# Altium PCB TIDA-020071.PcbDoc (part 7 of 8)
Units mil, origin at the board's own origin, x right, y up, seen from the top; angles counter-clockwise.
Board outline 5750 x 4050 mil, 6 copper layers (Top Layer, GND PLANE-1, SIGNAL LAYER, SIGNAL/POWER LAYER, GND PLANE-2, Bottom Layer), stack 59.616 mil thick; 776 components, 498 nets, 2205 pads, 871 vias.
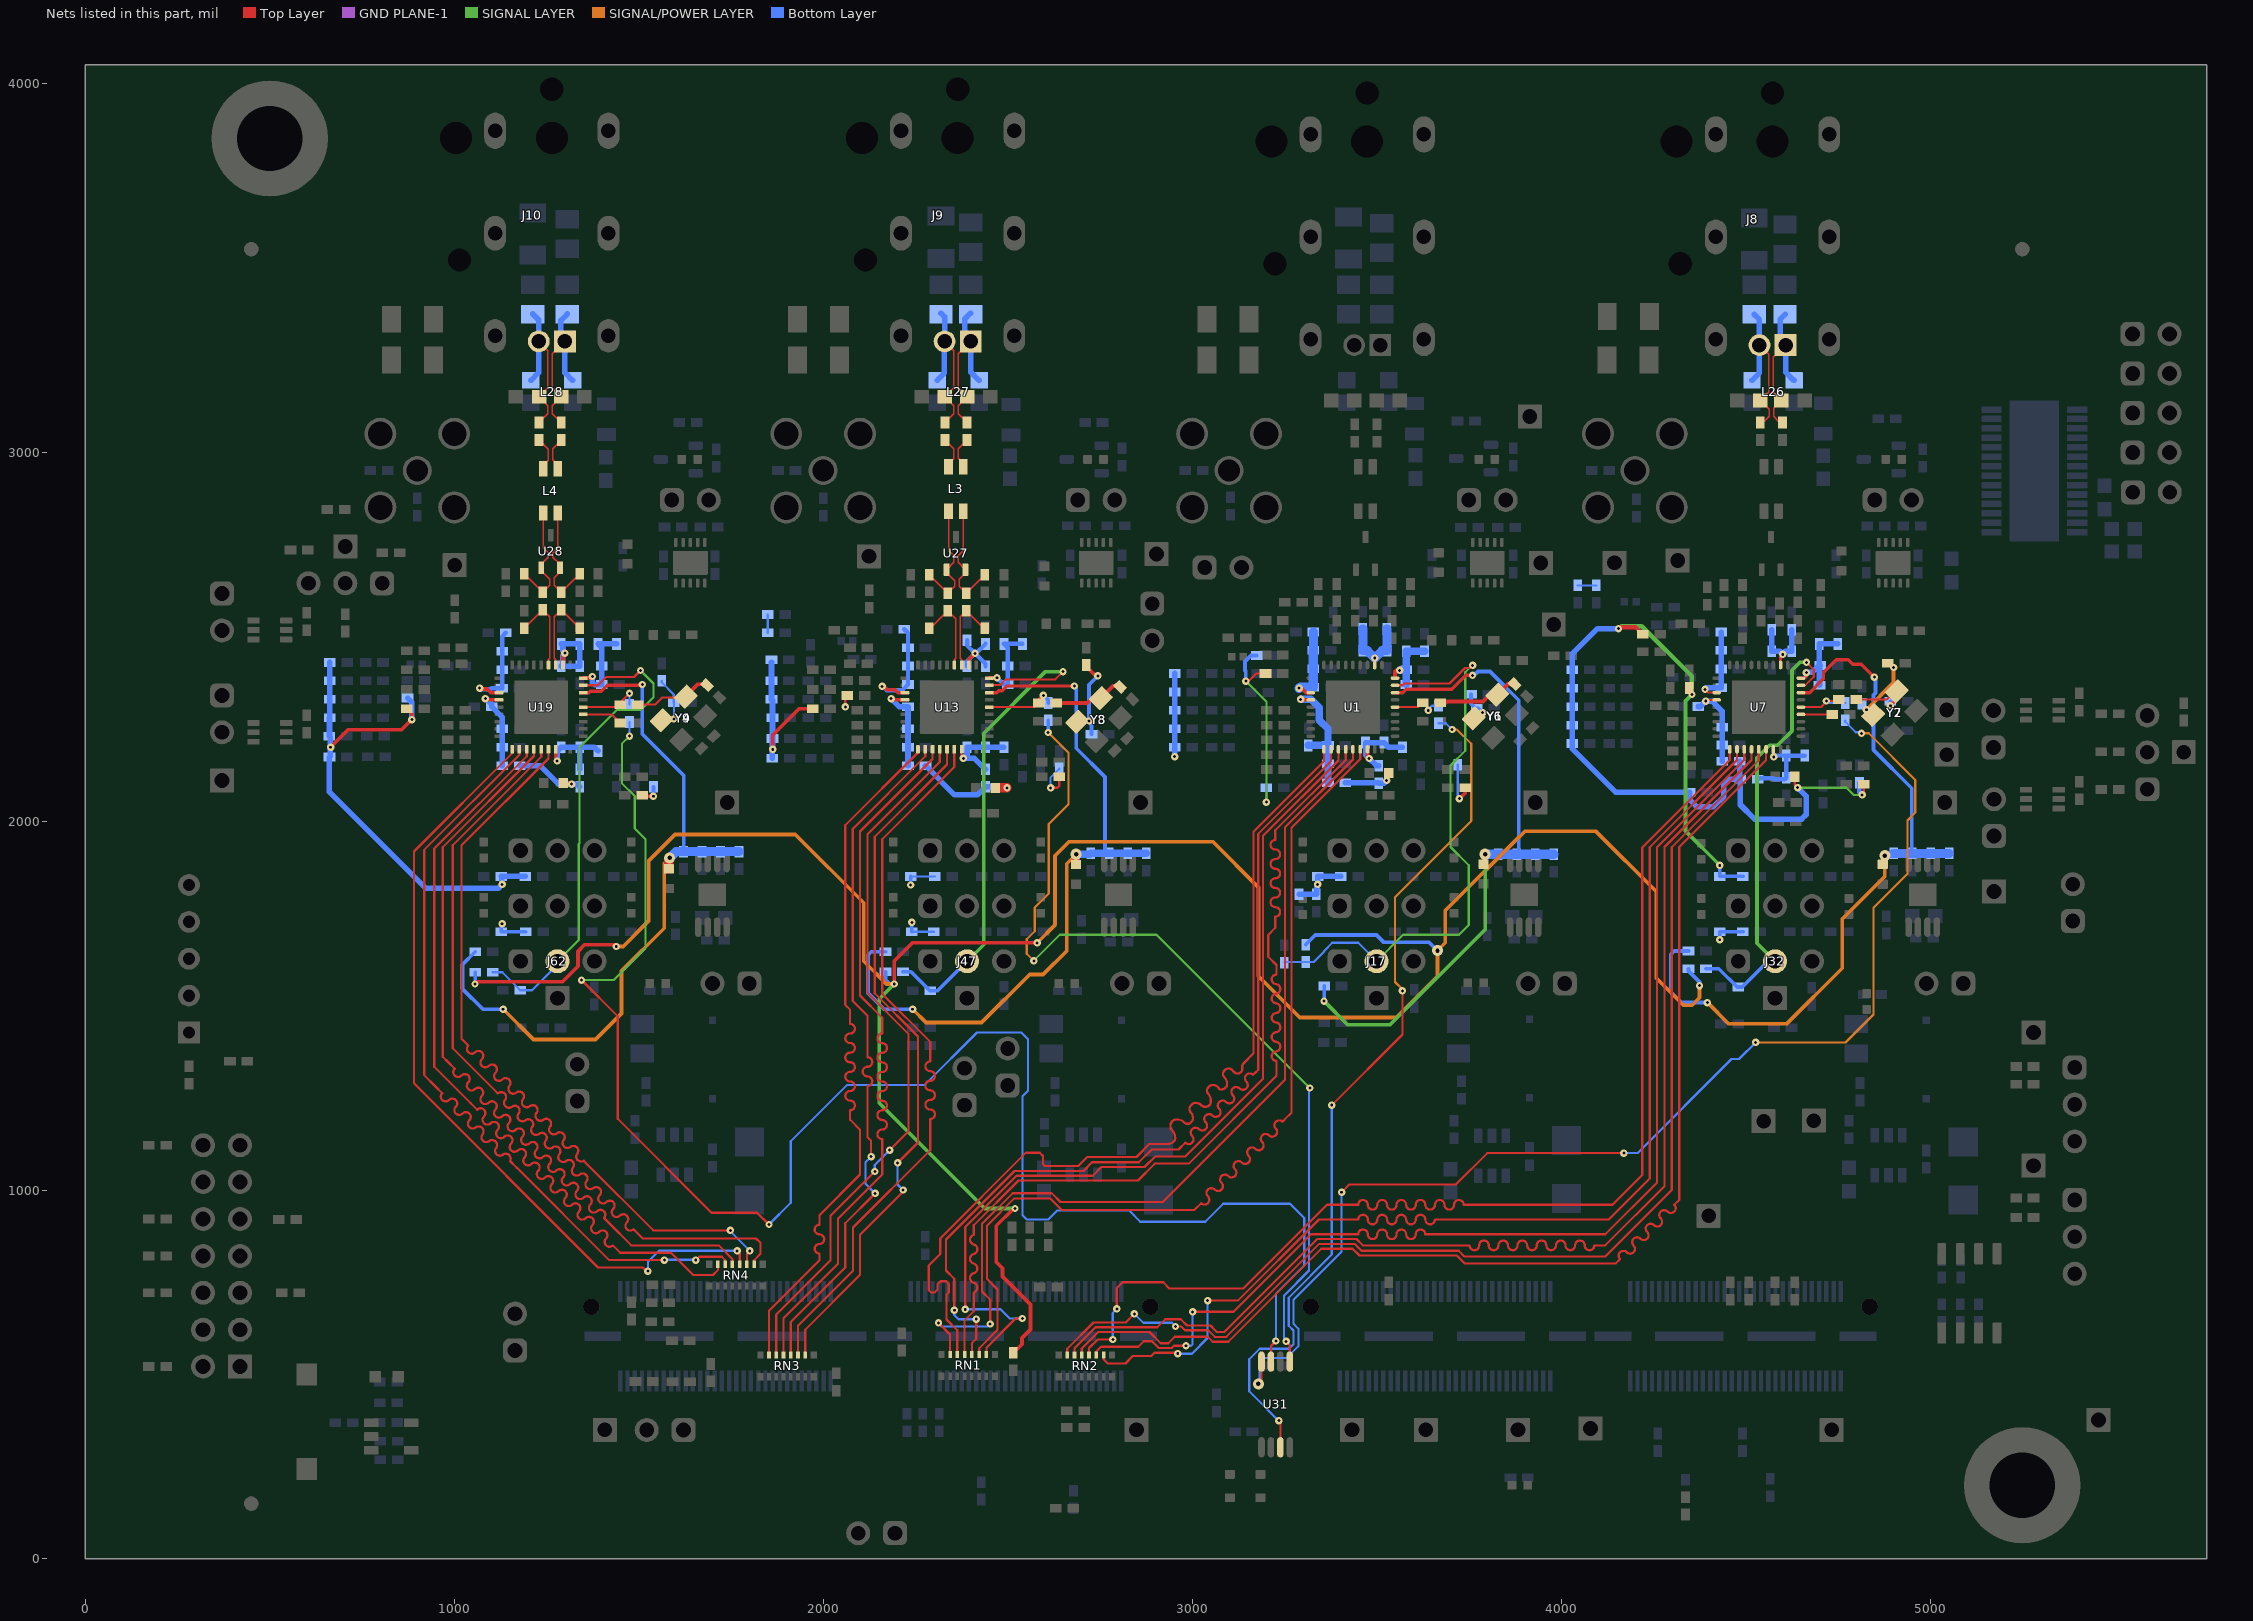
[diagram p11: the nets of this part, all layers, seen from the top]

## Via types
v1: diameter 20, hole 8, Top Layer to Bottom Layer, tented both sides, 637 vias
v2: diameter 30, hole 12, Top Layer to Bottom Layer, tented both sides, 105 vias
v3: diameter 19.68, hole 7.87, Top Layer to Bottom Layer, tented bottom, 68 vias
v4: diameter 19.68, hole 7.87, Top Layer to Bottom Layer, 25 vias
v5: diameter 24, hole 8, Top Layer to Bottom Layer, tented both sides, 24 vias
v6: diameter 19.68, hole 7.87, Top Layer to Bottom Layer, tented both sides, 12 vias

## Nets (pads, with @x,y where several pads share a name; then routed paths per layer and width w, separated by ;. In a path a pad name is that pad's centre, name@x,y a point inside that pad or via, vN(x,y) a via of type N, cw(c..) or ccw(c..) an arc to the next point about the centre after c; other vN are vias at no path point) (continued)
TRD2C_N: C152.1 D35.1 J8.2 L26.4 R237.2 | length 446.9
  Top Layer w4: J8.2@4537.64,3290 4562.5,3265.13 4562.5,3162.5 D35.1@4540,3140 4564,3116 4564,3096.56 4549.44,3082 4542,3082 C152.1@4540,3080
  Bottom Layer w15: L26.4@4517.42,3194.51 4537.32,3214.41 4537.32,3289.68 J8.2@4537.64,3290 4537.64,3359.16 R237.2@4523.48,3373.31
TRD2C_P: C153.1 D36.2 J8.1 L26.1 R236.2 | length 456.7
  Top Layer w4: C153.1@4600,3080 4598,3082 4590.56,3082 4576,3096.56 4576,3118.99 D36.2@4597.01,3140 4574.5,3162.5 4574.5,3256.5 4608,3290 J8.1@4608.5,3290
  Bottom Layer w15: R236.2@4607.16,3373.22 4594.29,3360.34 4594.29,3304.22 J8.1@4608.5,3290 4608.5,3216.63 4630.63,3194.51 L26.1@4631.59,3194.51
TRD3_N: C159.2 R243.2 U13.13 | length 227.3
  Top Layer w4: C159.2@2287.64,2522.76 2289.64,2524.76 2292.39,2524.76 R243.2@2337.64,2570 2339.64,2568 2359.35,2548.3 2359.35,2440.57 2355.51,2436.72 U13.13@2355.51,2422.91
TRD3_P: C160.1 R244.2 U13.12 | length 225
  Top Layer w4: U13.12@2375.2,2422.91 2375.2,2436.72 2371.35,2440.57 2371.35,2553.72 R244.2@2387.64,2570 2432.88,2524.76 2435.64,2524.76 C160.1@2437.64,2522.76
TRD3A_N: L3.4 R243.1 R245.1 U27.1 | length 324.4
  Top Layer w4: R245.1@2287.64,2667.24 R243.1@2337.64,2617.24 2356.64,2636.24 2356.64,2650.86 2334.41,2673.09 U27.1@2334.41,2681.42 2354,2701.01 2354,2719.2 2352.2,2721 2352.13,2721 2340,2733.13 L3.4@2340,2839.92
TRD3A_P: L3.1 R244.1 R246.2 U27.2 | length 322
  Top Layer w4: L3.1@2379.37,2839.92 2379.37,2732.5 2367.87,2721 2367.8,2721 2366,2719.2 2366,2701.01 U27.2@2385.59,2681.42 2385.59,2672.09 2368.64,2655.14 2368.64,2636.24 R244.1@2387.64,2617.24 R246.2@2437.64,2667.24
TRD3B_N: C163.2 L3.3 | length 88.2
  Top Layer w4: C163.2@2330,3032.76 2353.68,3009.07 2353.68,2982.18 2340,2968.5 L3.3@2340,2960
TRD3B_P: C164.2 L3.2 | length 88.5
  Top Layer w4: L3.2@2379.37,2960 2379.37,2969.63 2365.68,2983.31 2365.68,3008.44 C164.2@2390,3032.76
TRD3C_N: C163.1 D37.1 J9.2 L27.4 R248.2 | length 454.7
  Top Layer w4: J9.2@2329.13,3300 2354,3275.13 2354,3174 D37.1@2330,3150 2354,3126 2354,3104 C163.1@2330,3080
  Bottom Layer w15: L27.4@2308.91,3194.51 2328.82,3214.41 2328.82,3299.68 J9.2@2329.13,3300 2329.13,3366.55 R248.2@2319.11,3376.57
TRD3C_P: C164.1 D38.2 J9.1 L27.1 R247.2 | length 470.2
  Top Layer w4: C164.1@2390,3080 2366,3104 2366,3126 D38.2@2390,3150 2366,3174 2366,3266.5 2399.5,3300 J9.1@2400,3300
  Bottom Layer w15: R247.2@2399.79,3376.57 2383.22,3360 2383.22,3316.78 J9.1@2400,3300 2400,3216.63 2422.12,3194.51 L27.1@2423.09,3194.51
TRD4_N: C167.2 R251.2 U19.13 | length 230.2
  Top Layer w4: C167.2@1190,2522.76 R251.2@1240,2572.76 1259.35,2553.4 1259.35,2440.57 1255.51,2436.72 U19.13@1255.51,2422.91
TRD4_P: C168.2 R252.2 U19.12 | length 229.9
  Top Layer w4: U19.12@1275.2,2422.91 1275.2,2436.72 1271.35,2440.57 1271.35,2554.11 R252.2@1290,2572.76 C168.2@1340,2522.76
TRD4A_N: L4.4 R251.1 R253.1 U28.1 | length 317.2
  Top Layer w4: R253.1@1190,2670 R251.1@1240,2620 1259,2639 1259,2655.1 1235.92,2678.18 U28.1@1235.92,2686.42 1235.92,2695.5 1255.51,2715.09 1255.51,2726.94 1241.14,2741.32 L4.4@1241.14,2835.04
TRD4A_P: L4.1 R252.1 R254.1 U28.2 | length 313.8
  Top Layer w4: L4.1@1280.51,2835.04 1280.51,2755.69 1280.51,2739.94 1280.51,2739.11 1267.51,2726.11 1267.51,2715.49 1287.1,2695.9 U28.2@1287.1,2686.42 1287.1,2675.3 1271,2659.2 1271,2639 R252.1@1290,2620 R254.1@1340,2670
TRD4B_N: C171.2 L4.3 | length 93.6
  Top Layer w4: C171.2@1230,3032.76 1254.83,3007.93 1254.83,2977.83 1241.14,2964.14 L4.3@1241.14,2955.12
TRD4B_P: C172.2 L4.2 | length 92.9
  Top Layer w4: L4.2@1280.51,2955.12 1280.51,2965.39 1266.83,2979.07 1266.83,3009.58 C172.2@1290,3032.76
TRD4C_N: C171.1 D39.1 J10.2 L28.4 R256.2 | length 456.1
  Top Layer w4: J10.2@1229.13,3300 1254,3275.13 1254,3174 D39.1@1230,3150 1254,3126 1254,3104 C171.1@1230,3080
  Bottom Layer w15: L28.4@1207.48,3194.51 1208.44,3194.51 1229.08,3215.15 1229.08,3216.11 1229.13,3216.16 J10.2@1229.13,3300 1229.13,3358.13 R256.2@1212.98,3374.28
TRD4C_P: C172.1 D40.2 J10.1 L28.1 R255.2 | length 465.2
  Top Layer w4: C172.1@1290,3080 1266,3104 1266,3126 D40.2@1290,3150 1266,3174 1266,3266.7 1299.3,3300 J10.1@1300,3300
  Bottom Layer w15: R255.2@1306.77,3374.28 1289.41,3356.92 1289.41,3310.59 J10.1@1300,3300 1300,3215.2 1320.69,3194.51 L28.1@1321.65,3194.51
TX_CLK-1: RN1.14 U1.28 | length 2626.2
  Top Layer w6: RN1.14@2363.73,554.39 2363.73,620 2334.41,649.32 2334.41,716.51 2340.6,722.7 2340.6,745.47 2333.57,752.5 2318,752.5 2309.9,744.4 2309.9,729.8 2302.7,722.6 2292.02,722.6 2286,728.62 2286,795.5 2317.1,826.6 2317.1,868.46 2549.44,1100.8 2587,1100.8 2595.6,1092.2 2595.6,1070 2600.6,1065 2691.4,1065 2716.1,1089.7 2849.14,1089.7 2884.54,1125.1 2934.93,1125.1 ccw(c2934.93,1146.27) 2949.9,1131.3 ccw(c2939.28,1141.92) 2954.3,1141.92 ccw(c2928.11,1141.92) 2950.91,1154.81 ccw(c2928.11,1141.92) 2946.63,1160.44 cw(c2958.99,1172.81) 2941.51,1172.81 2941.51,1174.7 cw(c2958.21,1174.7) 2946.4,1186.51 cw(c2958.2,1174.72) 2958.2,1191.4 cw(c2958.2,1162.18) 2978.86,1182.84 ccw(c2987.65,1191.63) 2978.9,1182.8 ccw(c2987.65,1191.63) 2987.65,1179.2 ccw(c2987.65,1191.88) 2996.61,1182.91 2998.64,1184.93 ccw(c2990.27,1193.3) 3002.1,1193.3 3002.1,1196.4 ccw(c2982.3,1196.4) 3000.44,1204.34 ccw(c2982.3,1196.4) 2996.3,1210.4 cw(c3004.75,1218.85) 2992.8,1218.85 cw(c3007.89,1218.85) 2997.22,1229.52 3000.17,1232.47 cw(c3009.5,1223.15) 3009.5,1236.34 cw(c3009.5,1215.18) 3024.46,1230.14 ccw(c3036.15,1241.83) 3025.38,1229.28 ccw(c3036.15,1241.83) 3036.15,1225.3 ccw(c3036.15,1239.43) 3046.14,1229.44 ccw(c3035.61,1239.97) 3050.5,1239.97 3050.5,1243.78 ccw(c3025.58,1243.78) 3048.83,1252.73 ccw(c3025.58,1243.78) 3043.2,1261.4 cw(c3049.96,1268.16) 3040.4,1268.16 cw(c3057.4,1268.16) 3045.38,1280.18 cw(c3056.78,1268.78) 3056.78,1284.9 cw(c3056.78,1269.15) 3067.91,1280.29 3074.34,1273.86 ccw(c3078.1,1277.61) 3078.1,1272.3 ccw(c3078.1,1288.72) 3089.71,1277.11 3092.85,1280.25 ccw(c3087.9,1285.2) 3094.9,1285.2 3094.9,1287.42 ccw(c3070.32,1287.42) 3093,1296.9 ccw(c3070.32,1287.42) 3087.7,1304.8 cw(c3097.84,1314.94) 3083.5,1314.94 cw(c3096.2,1314.94) 3087.21,1323.91 3088.17,1324.87 cw(c3099.1,1313.95) 3099.1,1329.4 cw(c3099.1,1316.6) 3108.15,1325.65 3113.77,1320.03 ccw(c3123.5,1329.76) 3115.02,1318.92 ccw(c3123.5,1329.76) 3123.5,1316 ccw(c3123.5,1329.04) 3132.72,1319.82 ccw(c3125.28,1327.26) 3135.8,1327.26 3135.8,1335.17 cw(c3146.73,1335.17) 3139,1342.9 3166,1369.9 3166,1970.44 3357.09,2161.53 U1.28@3357.09,2194.57
TX_CLK-2: RN2.12 U7.28 | length 3216.6
  Top Layer w6: RN2.12@2720.67,553.15 2720.67,571.58 2744.09,595 v1(2785,595) ; v1(2796,678) 2796,734.7 2811.1,749.8 2921.56,749.8 2938.29,733.06 3138.36,733.06 3365.29,960 3450,960 cw(c3463,960) 3476,960 ccw(c3489,960) 3502,960 cw(c3515,960) 3528,960 ccw(c3541,960) 3554,960 cw(c3567,960) 3580,960 ccw(c3593,960) 3606,960 cw(c3619,960) 3632,960 ccw(c3645,960) 3658,960 cw(c3671,960) 3684,960 ccw(c3697,960) 3710,960 cw(c3723,960) 3736,960 3740,960 4139.2,960 4220,1040.8 4220,1928.42 4457.09,2165.5 U7.28@4457.09,2194.57
  Bottom Layer w6: v1(2785,595) 2785,667 v1(2796,678)
TX_CLK-3: RN3.15 U13.28 | length 2020
  Top Layer w6: RN3.15@1853.13,553.15 1853.13,673.13 1990,810 1990,827.79 cw(c1990,840.79) 1990,853.79 ccw(c1990,866.79) 1990,879.79 cw(c1990,892.79) 1990,905.79 1990,931.79 2100,1041.79 2100,1163.37 2073.09,1190.28 2073.09,1216.28 ccw(c2073.09,1229.28) 2073.09,1242.28 cw(c2073.09,1255.28) 2073.09,1268.28 ccw(c2073.09,1281.28) 2073.09,1294.28 cw(c2073.09,1307.28) 2073.09,1320.28 ccw(c2073.09,1333.28) 2073.09,1346.28 cw(c2073.09,1359.28) 2073.09,1372.28 ccw(c2073.09,1385.28) 2073.09,1398.28 cw(c2073.09,1411.28) 2073.09,1424.28 ccw(c2073.09,1437.28) 2073.09,1450.28 2073.09,1472.77 2073.09,1488.37 2060,1501.46 2060,1988.82 2257.09,2185.9 U13.28@2257.09,2194.57
TX_CLK-4: RN4.4 U19.28 | length 2179
  Top Layer w6: U19.28@1157.09,2194.57 1157.09,2183.82 891,1917.73 891,1289 1389.79,790.21 1511.27,790.21 1521.48,780 v1(1525,780) ; v1(1766.95,835.17) 1773.7,828.42 RN4.4@1773.7,799.05
  Bottom Layer w6: v1(1525,780) 1525,805 1555.17,835.17 v1(1766.95,835.17)
TX_CTRL-1: RN1.12 U1.29 | length 2514.3
  Top Layer w6: v1(2355.51,674.14) 2355.51,759.29 2332.9,781.9 2332.9,865.87 2518.87,1051.84 2705.54,1051.84 2728.9,1075.2 2855.51,1075.2 2890.26,1109.94 2963.14,1109.94 2981.53,1128.33 ccw(c2990.72,1137.52) 2999.91,1146.71 cw(c3009.1,1155.9) 3018.3,1165.1 ccw(c3027.49,1174.29) 3036.68,1183.48 cw(c3045.87,1192.67) 3055.07,1201.87 ccw(c3064.26,1211.06) 3073.45,1220.25 cw(c3082.64,1229.44) 3091.84,1238.64 ccw(c3101.03,1247.83) 3110.22,1257.02 cw(c3119.41,1266.21) 3128.61,1275.41 ccw(c3137.8,1284.6) 3146.99,1293.79 cw(c3156.18,1302.98) 3165.38,1312.17 3171.5,1318.3 3179.2,1326 3179.2,1965.26 3376.77,2162.83 U1.29@3376.77,2194.57 ; RN1.12@2403.1,554.39 2403.1,584.87 2415,596.76 v1(2415,650)
  Bottom Layer w6: v1(2355.51,674.14) 2355.51,661.47 2366.98,650 v1(2415,650)
TX_CTRL-2: RN2.10 U7.29 | length 3146
  Top Layer w6: RN2.10@2760.04,553.15 2760.04,540.98 2771.08,529.94 2819.33,529.94 2839.38,550 2889.14,550 2898.14,559 2958.5,559 v1(2961,556.5) ; v1(3041.9,700.2) 3123.88,700.2 3343.68,920 3450,920 cw(c3463,920) 3476,920 ccw(c3489,920) 3502,920 cw(c3515,920) 3528,920 ccw(c3541,920) 3554,920 cw(c3567,920) 3580,920 ccw(c3593,920) 3606,920 cw(c3619,920) 3632,920 ccw(c3645,920) 3658,920 3660,920 4128.9,920 4240,1031.1 4240,1928.79 4476.77,2165.57 U7.29@4476.77,2194.57
  Bottom Layer w6: v1(2961,556.5) 2999.5,556.5 3041.9,598.9 v1(3041.9,700.2)
TX_CTRL-3: RN3.12 U13.29 | length 1900.1
  Top Layer w6: RN3.12@1912.18,553.15 1912.18,642.18 2060,790 2060,910.07 v1(2140.73,990.8) ; v1(2130,1090.5) 2130,1132.83 2120,1142.83 2120,1270 2120,1282 ccw(c2120,1295) 2120,1308 cw(c2120,1321) 2120,1334 ccw(c2120,1347) 2120,1360 2120,1472.19 2080,1512.19 2080,1978.71 2276.77,2175.48 U13.29@2276.77,2194.57
  Bottom Layer w6: v1(2130,1090.5) 2114.57,1075.07 2114.57,1016.96 v1(2140.73,990.8)
TX_CTRL-4: RN4.6 U19.29 | length 2163.2
  Top Layer w6: U19.29@1176.77,2194.57 1176.77,2180 918.62,1921.85 918.62,1311.38 949.19,1280.81 967.58,1262.42 ccw(c976.77,1253.23) 985.96,1244.04 cw(c995.15,1234.85) 1004.35,1225.65 ccw(c1013.54,1216.46) 1022.73,1207.27 cw(c1031.92,1198.08) 1041.12,1188.88 ccw(c1050.31,1179.69) 1059.5,1170.5 cw(c1066.15,1158.76) 1077.89,1152.11 ccw(c1087.08,1142.92) 1096.27,1133.73 cw(c1102.76,1121.83) 1114.66,1115.34 ccw(c1123.85,1106.15) 1133.04,1096.96 cw(c1139.53,1085.06) 1151.42,1078.57 1169.81,1060.19 1170,1060 1420,810 v1(1569.86,810) ; v1(1654.71,810) 1655.1,810 1664,818.9 1725.14,818.9 1734.33,809.71 RN4.6@1734.33,799.05
  Bottom Layer w6: v1(1569.86,810) 1571.04,811.18 1653.52,811.18 v1(1654.71,810)
TX_D0-1: RN1.11 U1.33 | length 2600.3
  Top Layer w6: RN1.11@2422.79,554.39 2422.79,571.53 2472.76,621.5 2472.76,730.24 2443.8,759.2 2443.8,903.24 2517.96,977.4 2614.9,977.4 2646.3,946 3006,946 3024.38,964.38 ccw(c3033.58,973.58) 3042.77,982.77 cw(c3051.96,991.96) 3061.15,1001.15 ccw(c3070.35,1010.35) 3079.54,1019.54 cw(c3088.73,1028.73) 3097.92,1037.92 ccw(c3107.12,1047.12) 3116.31,1056.31 cw(c3125.5,1065.5) 3134.69,1074.69 ccw(c3143.89,1083.89) 3153.08,1093.08 cw(c3162.27,1102.27) 3171.46,1111.46 ccw(c3180.66,1120.65) 3189.85,1129.85 cw(c3199.04,1139.04) 3208.23,1148.23 ccw(c3217.42,1157.42) 3226.62,1166.62 cw(c3235.81,1175.81) 3245,1185 3250,1190 3250,1190.25 3269.1,1209.35 3269.1,1981.62 3455.51,2168.03 U1.33@3455.51,2194.57
TX_D0-2: RN2.13 U7.33 | length 3309.7
  Top Layer w6: RN2.13@2700.99,553.15 2700.99,570.28 2745.71,615 2884.64,615 2914.64,585 2935.36,585 2952.86,602.5 3042.45,602.5 3055.95,589 3098,589 3350,841 3434.91,841 3453.53,822.38 3575.24,822.38 3575.3,822.44 3598.49,822.44 3598.55,822.38 3717.08,822.38 3738.27,801.19 4147.96,801.19 4156.77,810 4159.69,812.92 cw(c4168.89,822.11) 4178.08,831.31 ccw(c4187.27,840.5) 4196.46,849.69 cw(c4205.66,858.88) 4214.85,868.08 ccw(c4224.04,877.27) 4233.23,886.46 cw(c4242.43,895.65) 4251.62,904.85 ccw(c4260.81,914.04) 4270,923.23 cw(c4279.19,932.42) 4288.39,941.61 ccw(c4297.58,950.81) 4306.77,960 4320,973.23 4320,1929.5 4555.51,2165.01 U7.33@4555.51,2194.57
TX_D0-3: RN3.11 U13.33 | length 2013.6
  Top Layer w6: RN3.11@1931.87,553.15 1931.87,631.87 2081.12,781.12 2081.12,898.61 2290,1107.5 2290,1166.23 2290,1192.23 ccw(c2290,1205.23) 2290,1218.23 cw(c2290,1231.23) 2290,1244.23 ccw(c2290,1257.23) 2290,1270.23 cw(c2290,1283.23) 2290,1296.23 ccw(c2290,1309.23) 2290,1322.23 cw(c2290,1335.23) 2290,1348.23 2290,1370 2290,1401.52 2160,1531.52 2160,1951.01 2355.51,2146.52 U13.33@2355.51,2194.57
TX_D0-4: RN4.3 U19.33 | length 2161.7
  Top Layer w6: U19.33@1255.51,2194.57 1255.51,2169.76 1020,1934.25 1020,1410 1038.38,1391.61 ccw(c1047.58,1382.42) 1056.77,1373.23 cw(c1065.96,1364.04) 1075.15,1354.85 ccw(c1084.35,1345.65) 1093.54,1336.46 cw(c1102.73,1327.27) 1111.92,1318.08 ccw(c1121.12,1308.88) 1130.31,1299.69 cw(c1139.5,1290.5) 1148.69,1281.31 ccw(c1160.27,1274.5) 1167.08,1262.92 cw(c1176.27,1253.73) 1185.46,1244.54 ccw(c1197.04,1237.73) 1203.85,1226.15 cw(c1213.04,1216.96) 1222.23,1207.77 ccw(c1233.81,1200.96) 1240.62,1189.38 cw(c1249.81,1180.19) 1259,1171 ccw(c1270.58,1164.19) 1277.39,1152.61 cw(c1286.58,1143.42) 1295.77,1134.23 ccw(c1307.35,1127.42) 1314.16,1115.84 cw(c1323.35,1106.65) 1332.54,1097.46 ccw(c1344.12,1090.65) 1350.93,1079.07 1360,1070 1539.39,890.61 v1(1748.35,890.61) ; RN4.3@1793.38,799.05 1793.38,827.43 v1(1801.12,835.17)
  Bottom Layer w6: v1(1748.35,890.61) 1748.35,887.93 v1(1801.12,835.17)
TX_D1-1: RN1.15 U1.32 | length 2501.7
  Top Layer w6: v1(2312.55,639.79) 2312.76,640 2344.05,608.71 RN1.15@2344.05,554.39 ; v1(2452.76,636.83) 2452.76,702.74 2430.8,724.7 2430.8,908.62 2513.68,991.5 2619.19,991.5 2643.32,967.37 2920.77,967.37 3252,1298.6 3252,1982.9 3435.83,2166.73 U1.32@3435.83,2194.57
  Bottom Layer w6: v1(2312.55,639.79) 2322.35,630 2445.93,630 v1(2452.76,636.83)
TX_D1-2: RN2.15 U7.32 | length 3205.4
  Top Layer w6: RN2.15@2661.62,553.15 2661.62,570 2732.62,641 2819.86,641 v1(2843.37,664.5) ; v1(2954.85,630) 2970.67,630 2980.67,620 3043.33,620 3061.33,602 3092.62,602 3344.62,854 3440.3,854 3458.92,835.38 3569.86,835.38 3569.91,835.44 3603.88,835.44 3603.94,835.38 3722.46,835.38 3737.84,820 4119.66,820 4300,1000.33 4300,1929.12 4535.83,2164.95 U7.32@4535.83,2194.57
  Bottom Layer w6: v1(2843.37,664.5) 2867.87,640 2944.85,640 v1(2954.85,630)
TX_D1-3: RN3.10 U13.32 | length 1912
  Top Layer w6: RN3.10@1951.56,553.15 1951.56,621.55 2100,770 2100,878.43 2219.21,997.65 v1(2216.86,1000) ; v1(2201.76,1073.47) 2257.09,1128.8 2257.09,1416.04 2140,1533.13 2140,1957.24 2335.83,2153.07 U13.32@2335.83,2194.57
  Bottom Layer w6: v1(2201.76,1073.47) 2201.76,1015.1 v1(2216.86,1000)
TX_D1-4: RN4.2 U19.32 | length 2285.6
  Top Layer w6: U19.32@1235.83,2194.57 1235.83,2174.44 996.14,1934.76 996.14,1383.86 1115,1265 1118.47,1261.53 cw(c1127.67,1252.33) 1136.86,1243.14 ccw(c1148.44,1236.34) 1155.24,1224.76 cw(c1164.44,1215.56) 1173.63,1206.37 ccw(c1185.21,1199.57) 1192.01,1187.99 cw(c1201.21,1178.79) 1210.4,1169.6 ccw(c1221.98,1162.8) 1228.78,1151.22 cw(c1237.97,1142.02) 1247.17,1132.83 ccw(c1258.75,1126.03) 1265.55,1114.45 cw(c1274.74,1105.26) 1283.94,1096.06 ccw(c1295.52,1089.26) 1302.32,1077.68 cw(c1311.51,1068.49) 1320.71,1059.29 ccw(c1332.29,1052.49) 1339.09,1040.91 cw(c1348.28,1031.72) 1357.48,1022.52 ccw(c1369.06,1015.72) 1375.86,1004.14 cw(c1385.05,994.95) 1394.25,985.75 ccw(c1403.44,976.56) 1412.63,967.37 cw(c1421.82,958.18) 1431.01,948.98 ccw(c1440.21,939.79) 1449.4,930.6 cw(c1458.59,921.41) 1467.78,912.22 ccw(c1476.98,903.02) 1486.17,893.83 1511.15,868.85 1818.21,868.85 1830,857.06 1830,826.93 1813.07,810 RN4.2@1813.07,799.05
TX_D2-1: RN1.13 U1.31 | length 2616.6
  Top Layer w6: RN1.13@2383.42,554.39 2383.42,646.7 2408.4,671.68 2408.4,698.3 2408.4,722.61 ccw(c2404.11,735.61) 2408.4,748.61 cw(c2411.46,761.61) 2408.4,774.61 ccw(c2404.11,787.61) 2408.4,800.61 cw(c2411.46,813.61) 2408.4,826.61 ccw(c2404.11,839.61) 2408.4,852.61 cw(c2411.46,865.61) 2408.4,878.61 2408.4,904.61 2529.64,1025.84 2853.14,1025.84 2898.8,1071.5 2990.5,1071.5 3228.6,1309.6 3228.6,1324.3 3228.6,1349.9 cw(c3228.6,1362.9) 3228.6,1375.9 ccw(c3225.68,1388.9) 3228.6,1401.9 cw(c3228.6,1414.9) 3228.6,1427.9 ccw(c3225.68,1440.9) 3228.6,1453.9 cw(c3228.6,1466.9) 3228.6,1479.9 ccw(c3225.68,1492.9) 3228.6,1505.9 cw(c3228.6,1518.9) 3228.6,1531.9 ccw(c3225.68,1544.9) 3228.6,1557.9 cw(c3228.6,1570.9) 3228.6,1583.9 3228.6,1609.9 3206.3,1632.2 3206.3,1691.4 3225.5,1710.6 3225.5,1731.4 3225.5,1740.79 ccw(c3225.5,1753.79) 3225.5,1766.79 cw(c3225.5,1779.79) 3225.5,1792.79 ccw(c3225.5,1805.79) 3225.5,1818.79 cw(c3225.5,1831.79) 3225.5,1844.79 ccw(c3225.5,1857.79) 3225.5,1870.79 cw(c3225.5,1883.79) 3225.5,1896.79 ccw(c3225.5,1909.79) 3225.5,1922.79 cw(c3225.5,1935.79) 3225.5,1948.79 3225.5,1974.79 3416.14,2165.43 U1.31@3416.14,2194.57
TX_D2-2: RN2.14 U7.31 | length 3317.5
  Top Layer w6: RN2.14@2681.3,553.15 2681.3,571.3 2738,628 2905.39,628 2927.39,650 2969.06,650 2986.06,633 3049.57,633 3055,627.57 3055,626.72 3066.72,615 3087.23,615 3339.23,867 3445.68,867 3462.68,850 3740,850 3752,850 ccw(c3765,850) 3778,850 cw(c3791,850) 3804,850 ccw(c3817,850) 3830,850 cw(c3843,850) 3856,850 ccw(c3869,850) 3882,850 cw(c3895,850) 3908,850 ccw(c3921,850) 3934,850 cw(c3947,850) 3960,850 ccw(c3973,850) 3986,850 cw(c3999,850) 4012,850 ccw(c4025,850) 4038,850 cw(c4051,850) 4064,850 ccw(c4077,850) 4090,850 4120,850 4280,1010 4280,1929.55 4516.14,2165.7 U7.31@4516.14,2194.57
TX_D2-3: RN3.14 U13.31 | length 1917
  Top Layer w6: RN3.14@1872.82,553.15 1872.82,662.81 2019.86,809.86 2019.86,930.21 v1(2140,1050.34) ; v1(2180,1107.89) 2230.98,1158.86 2230.98,1423.77 2120,1534.75 2120,1964.05 2316.14,2160.19 U13.31@2316.14,2194.57
  Bottom Layer w6: v1(2140,1050.34) 2140,1067.87 v1(2180,1107.89)
TX_D2-4: RN4.5 U19.31 | length 2288.5
  Top Layer w6: U19.31@1216.14,2194.57 1216.14,2176.14 969,1929 969,1361 982.98,1347.02 1001.37,1328.63 ccw(c1010.56,1319.44) 1019.75,1310.25 cw(c1028.94,1301.06) 1038.14,1291.86 ccw(c1047.33,1282.67) 1056.52,1273.48 cw(c1065.71,1264.29) 1074.9,1255.09 ccw(c1084.1,1245.9) 1093.29,1236.71 cw(c1102.48,1227.52) 1111.67,1218.33 ccw(c1120.87,1209.13) 1130.06,1199.94 cw(c1139.25,1190.75) 1148.44,1181.56 ccw(c1157.64,1172.36) 1166.83,1163.17 cw(c1176.02,1153.98) 1185.21,1144.79 ccw(c1194.41,1135.59) 1203.6,1126.4 cw(c1212.79,1117.21) 1221.98,1108.02 ccw(c1231.18,1098.82) 1240.37,1089.63 cw(c1249.56,1080.44) 1258.75,1071.25 ccw(c1267.94,1062.05) 1277.14,1052.86 cw(c1286.33,1043.67) 1295.52,1034.48 ccw(c1304.71,1025.28) 1313.91,1016.09 cw(c1323.1,1006.9) 1332.29,997.71 ccw(c1341.48,988.52) 1350.68,979.32 cw(c1359.87,970.13) 1369.06,960.94 ccw(c1378.25,951.75) 1387.45,942.55 cw(c1396.64,933.36) 1405.83,924.17 1419.35,910.65 1480,850 1717.16,850 1754.01,813.15 RN4.5@1754.01,799.05
TX_D3-1: RN1.10 U1.30 | length 2488
  Top Layer w6: v1(2385.11,676.67) 2385.11,899.7 2524.25,1038.84 2730.44,1038.84 2753.8,1062.2 2871.12,1062.2 2899.82,1090.9 2981.4,1090.9 3192.2,1301.7 3192.2,1959.87 3396.46,2164.13 U1.30@3396.46,2194.57 ; RN1.10@2442.47,554.39 2442.47,572.83 2521.43,651.78 v1(2540,651.78)
  Bottom Layer w6: v1@2385.14,676.64 2480.6,676.64 2505.46,651.78 v1(2540,651.78)
TX_D3-2: RN2.11 U7.30 | length 3161.2
  Top Layer w6: RN2.11@2740.36,553.15 2740.36,562.37 2752.99,575 2854.17,575 2869.17,590 2891.26,590 2909.26,572 2944.66,572 2950.57,577.9 v1(2983.39,577.9) ; v1(3001.38,670) 3112.06,670 3322.06,880 3450,880 cw(c3463,880) 3476,880 ccw(c3489,880) 3502,880 cw(c3515,880) 3528,880 ccw(c3541,880) 3554,880 cw(c3567,880) 3580,880 ccw(c3593,880) 3606,880 cw(c3619,880) 3632,880 3640,880 4120,880 4260,1020 4260,1929.17 4496.46,2165.63 U7.30@4496.46,2194.57
  Bottom Layer w6: v1(2983.39,577.9) 2997.11,577.9 3001.38,582.17 v1(3001.38,670)
TX_D3-3: RN3.13 U13.30 | length 2021.7
  Top Layer w6: RN3.13@1892.5,553.15 1892.5,652.5 2040,800 2040,922.06 2160,1042.06 2160,1120 2160,1138 cw(c2160,1151) 2160,1164 ccw(c2160,1177) 2160,1190 cw(c2160,1203) 2160,1216 ccw(c2160,1229) 2160,1242 cw(c2160,1255) 2160,1268 ccw(c2160,1281) 2160,1294 cw(c2160,1307) 2160,1320 ccw(c2160,1333) 2160,1346 cw(c2160,1359) 2160,1372 ccw(c2160,1385) 2160,1398 cw(c2160,1411) 2160,1424 2160,1450 2160,1467.05 2100,1527.05 2100,1971.89 2296.46,2168.35 U13.30@2296.46,2194.57
TX_D3-4: RN4.7 U19.30 | length 2284.9
  Top Layer w6: U19.30@1196.46,2194.57 1196.46,2175.88 946,1925.42 946,1334 1045,1235 1062.3,1217.69 cw(c1071.5,1208.5) 1080.69,1199.31 ccw(c1090,1190.23) 1099.07,1180.93 cw(c1108.27,1171.73) 1117.46,1162.54 ccw(c1126.65,1153.35) 1135.84,1144.16 cw(c1145.04,1134.96) 1154.23,1125.77 ccw(c1163.42,1116.58) 1172.61,1107.39 cw(c1181.81,1098.19) 1191,1089 ccw(c1200.19,1079.81) 1209.38,1070.62 cw(c1218.58,1061.42) 1227.77,1052.23 ccw(c1236.96,1043.04) 1246.15,1033.85 cw(c1255.34,1024.65) 1264.54,1015.46 ccw(c1273.73,1006.27) 1282.92,997.08 cw(c1292.11,987.89) 1301.31,978.69 ccw(c1310.5,969.5) 1319.69,960.31 cw(c1328.88,951.12) 1338.08,941.92 ccw(c1347.27,932.73) 1356.46,923.54 cw(c1365.65,914.35) 1374.85,905.15 ccw(c1384.04,895.96) 1393.23,886.77 cw(c1402.42,877.58) 1411.62,868.38 ccw(c1420.81,859.19) 1430,850 1450,830 1587.58,830 1648.06,769.53 1701.25,769.53 1714.64,782.92 RN4.7@1714.64,799.05
V_GND1: C1.1 R24.2 R77.1 Y1.4 Y6.4 | length 93.3
  Top Layer w10: Y6.4@3768.48,2276.43 3769.84,2276.43 v1(3787.42,2294)
  Bottom Layer w10: R24.2@3755.77,2343.41 3755.77,2317.77 3767.73,2305.82 R77.1@3771.67,2305.82 3775.61,2305.82 v1(3787.42,2294)
V_GND2: C35.1 R81.2 R114.1 Y2.4 Y7.4 | length 165.6
  Top Layer w10: R81.2@4885.39,2427.99 4889.32,2427.99 v1(4901.13,2416.18)
  SIGNAL/POWER LAYER w10: v1(4827.55,2301.69) 4901.13,2375.28 v1(4901.13,2416.18)
V_GND3: C68.1 R115.2 R130.1 Y3.4 Y8.4 | length 237.8
  Top Layer w10: Y3.4@2688.78,2269.26 2691.57,2272.05 2719.69,2272.05 v1(2720.71,2271.03) ; R115.2@2713.07,2422.94 2713.07,2419 2736.8,2395.27 2742.53,2395.27 v1(2744.45,2393.36)
  Bottom Layer w10: v1(2720.71,2271.03) 2720.71,2369.62 v1(2744.45,2393.36) ; R130.1@2727.17,2235.61 2727.17,2261.86
V_GND4: C69.1 R134.2 R151.1 Y4.4 Y9.4 | length 150.8
  Top Layer w6: Y4.4@1563.05,2273.33 1566.28,2276.56 v1(1595.57,2276.56)
  Bottom Layer w6: R134.2@1562.35,2379.77 1562.35,2375.84 1595.11,2343.08 R151.1@1595.11,2320.66 1595.57,2320.2 v1(1595.57,2276.56)
VDDp9-1: C10.1 C15.1 C20.1 R39.1 U1.9 | length 189.7
  Top Layer w10: U1.9@3550,2387.48 3550,2405.27 3553.23,2408.5 v1(3562.4,2408.5)
  Bottom Layer w20: v1(3562.4,2408.5) 3578.5,2408.5 C15.1@3580,2410 ; C10.1@3580,2370 C15.1@3580,2410 ; R39.1@3630,2460 C20.1@3580,2460 C15.1@3580,2410
VDDp9-2: C44.1 C49.1 C54.1 R92.1 U7.9 | length 236.9
  Top Layer w9: U7.9@4650,2387.48 4659.83,2387.48 4664.52,2392.17 v1@4664.52,2402
  Bottom Layer w15: v1(4664.56,2402) 4666.48,2403.91 4681.1,2403.91 4698.81,2421.62 C49.1@4702.75,2421.62 ; C54.1@4700.36,2367.79 4700.36,2419.24 C49.1@4702.75,2421.62 ; R92.1@4750,2480 C44.1@4700,2480 4700,2424.37 C49.1@4702.75,2421.62
VDDp9-3: C78.1 C83.1 C88.1 R145.1 U13.9 | length 226.8
  Top Layer w10: U13.9@2450,2387.48 2470.24,2387.48 v1(2471.11,2388.35) v1@2474.41,2391.65
  Bottom Layer w12: v1(2471.11,2388.35) 2489.46,2370 C88.1@2500,2370 C83.1@2500,2420 2500,2470 C78.1@2490,2480 R145.1@2540,2480
VDDp9-4: C112.1 C117.1 C122.1 R198.1 U19.9 | length 234
  Top Layer w10: U19.9@1350,2387.48 1370.24,2387.48 v1(1374.41,2391.65)
  Bottom Layer w15: v1(1374.41,2391.65) 1374.41,2376 1380.41,2370 C122.1@1400,2370 C117.1@1400,2420 1400,2470 C112.1@1390,2480 R198.1@1440,2480
VDDp11-1: C12.1 C17.1 C22.1 R41.1 U1.11 | length 218.2
  Top Layer w10: U1.11@3494.88,2422.91 3495,2423.03 v1(3495,2442)
  Bottom Layer w25: C17.1@3462.66,2520.38 3462.77,2520.27 3462.77,2462.07 C12.1@3462.66,2461.97 3475.03,2461.97 v1(3495,2442) 3514.97,2461.97 C22.1@3528,2461.97 3528,2519.65 R41.1@3527.28,2520.38
VDDp11-2: C46.1 C51.1 C56.1 R94.1 U7.11 | length 209.2
  Top Layer w8: U7.11@4594.88,2422.91 4594.88,2446.09 v1(4600.79,2452)
  Bottom Layer w15: C46.1@4571.23,2518.74 C56.1@4571.23,2460.15 4592.63,2460.15 v1(4600.79,2452) 4608.94,2460.15 C51.1@4625,2460.15 R94.1@4625,2518.74
VDDp11-3: C80.1 C85.1 C90.1 R147.1 U13.11 | length 211.5
  Top Layer w10: U13.11@2394.88,2422.91 2394.88,2437.64 v1(2411.65,2454.41)
  Bottom Layer w12: C90.1@2390,2420 2390,2432.76 v1(2411.65,2454.41) ; R147.1@2390,2490 2390,2476.06 v1(2411.65,2454.41) ; C85.1@2440,2420 2440,2426.06 v1(2411.65,2454.41) ; C80.1@2440,2480 2414.41,2454.41 v1(2411.65,2454.41)
VDDp11-4: C114.1 C119.1 C124.1 R200.1 U19.11 | length 262.5
  Top Layer w10: U19.11@1294.88,2422.91 1294.88,2449.88 v1(1300,2455)
  Bottom Layer w15: C124.1@1290,2420 C119.1@1340,2420 R200.1@1340,2480 C114.1@1290,2480 1294.31,2475.69 1294.31,2462.04 1300,2456.35 v1(1300,2455) 1300,2453.65 1294.31,2447.96 1294.31,2424.31 C124.1@1290,2420
VDDp21-1: C11.1 C16.1 C21.1 R40.1 U1.21 | length 227.5
  Top Layer w10: v1(3290,2360) 3292,2362 3294.38,2362 3294.38,2361.66 3307.92,2348.11 U1.21@3321.65,2348.11
  Bottom Layer w25: v1(3290,2360) 3292.76,2362.76 C11.1@3328.28,2362.76 C16.1@3328.28,2412.76 C21.1@3328.28,2462.76 3328.62,2463.09 R40.1@3328.62,2512.28
VDDp21-2: C45.1 C50.1 C55.1 R93.1 U7.21 | length 231.7
  Top Layer w6: v1(4390.08,2356.97) 4398.94,2348.11 U7.21@4421.65,2348.11
  Bottom Layer w15: v1(4390.08,2356.97) 4394.25,2361.14 C55.1@4433.62,2361.14 C50.1@4433.62,2412.11 C45.1@4433.62,2463.2 R93.1@4433.62,2512.28
VDDp21-3: C79.1 C84.1 C89.1 R146.1 U13.21 | length 303.2
  Top Layer w10: v1(2160,2365) 2164.2,2365 2173.32,2355.88 2194.72,2355.88 2202.49,2348.11 U13.21@2221.65,2348.11
  Bottom Layer w12: v1(2160,2365) 2162.16,2365 2172.29,2354.88 2214.88,2354.88 C89.1@2230,2370 C84.1@2230,2420 C79.1@2230,2470 2230,2510 R146.1@2220,2520
VDDp21-4: C113.1 C118.1 C123.1 R199.1 U19.21 | length 274.5
  Top Layer w10: v1(1069.2,2360) 1071.2,2358 1089.09,2358 1098.98,2348.11 U19.21@1121.65,2348.11
  Bottom Layer w12: v1(1069.2,2360) 1072.2,2357 1098.11,2357 1101.11,2360 C123.1@1129.53,2360 1130,2360.47 C118.1@1130,2410 C113.1@1130,2460 1130,2500 R199.1@1140,2510
VDDp22-1: C13.1 C18.1 C23.1 R42.1 U1.22 | length 355.7
  Top Layer w10: v1(3294,2330) 3295.57,2328.42 U1.22@3321.65,2328.42
  Bottom Layer w20: v1(3294,2330) 3322.19,2330 3344.41,2307.78 3344.41,2273.57 3368.11,2249.87 C18.1@3368.11,2205 ; C13.1@3314.41,2204.72 3314.68,2205 C18.1@3368.11,2205 ; R42.1@3368.11,2103.62 C23.1@3368.11,2155 C18.1@3368.11,2205
VDDp22-2: C47.1 C52.1 C57.1 R95.1 U7.22 | length 249.4
  Top Layer w6: v1(4391.99,2325.11) 4395.3,2328.42 U7.22@4421.65,2328.42
  Bottom Layer w15: C57.1@4371.62,2310.5 4377.38,2310.5 v1(4391.99,2325.11) 4408.89,2325.11 4436.38,2297.62 C52.1@4436.38,2254.14 C47.1@4436.38,2206.32 4437.24,2205.45 R95.1@4437.24,2161.8
VDDp22-3: C81.1 C86.1 C91.1 R148.1 U13.22 | length 253
  Top Layer w10: v1(2184.42,2331.56) 2187.93,2331.56 2191.06,2328.42 U13.22@2221.65,2328.42
  Bottom Layer w15: v1(2184.42,2331.56) 2205.98,2310 C91.1@2230,2310 C86.1@2230,2250 C81.1@2230,2200 R148.1@2230,2150
VDDp22-4: C115.1 C120.1 C125.1 R201.1 U19.22 | length 241
  Top Layer w10: v1(1084.42,2331.56) 1087.93,2331.56 1091.06,2328.42 U19.22@1121.65,2328.42
  Bottom Layer w15: v1(1084.42,2331.56) 1087.93,2331.56 1101.62,2317.86 C125.1@1101.62,2310 1130,2281.62 C120.1@1130,2250 C115.1@1130,2200 R201.1@1130,2150
VDDp34-1: C14.1 C19.1 C24.1 R43.1 U1.34 | length 213.5
  Top Layer w10: U1.34@3475.2,2194.57 3475.2,2174.05 v1(3479.75,2169.5)
  Bottom Layer w15: R43.1@3505.62,2150 3499.25,2150 v1(3479.75,2169.5) 3470,2179.25 C14.1@3470,2212.76 C19.1@3520,2212.76 3532.76,2200 C24.1@3570,2200
VDDp34-2: C48.1 C53.1 C58.1 R96.1 U7.34 | length 248.1
  Top Layer w8: U7.34@4575.2,2194.57 4575.2,2175.12 v1(4576.39,2173.94)
  Bottom Layer w12: R96.1@4532.83,2113.63 4535.32,2116.12 4573.9,2116.12 4576.4,2113.63 4606.27,2113.63 C48.1@4610,2117.36 C58.1@4610,2177.76 ; v1(4576.39,2173.94) 4580.21,2177.76 C58.1@4610,2177.76 ; C53.1@4660.55,2177.51 4610.25,2177.51 C58.1@4610,2177.76
VDDp34-3: C82.1 C87.1 C92.1 R149.1 U13.34 | length 233.5
  Top Layer w6: U13.34@2375.2,2194.57 2375.2,2179.21 2380,2174.41 2380,2170 v1(2379.91,2169.91)
  GND PLANE-1 w6: v1(2379.91,2169.91) v1@2380,2170
  Bottom Layer w15: R149.1@2440,2140 2410.09,2169.91 v1(2379.91,2169.91) 2390,2180 C92.1@2390,2200 C87.1@2440,2200 C82.1@2490,2200
VDDp34-4: C116.1 C121.1 C126.1 R202.1 U19.34 | length 239
  Top Layer w10: U19.34@1275.2,2194.57 1275.2,2166.83 v1(1279.12,2162.9)
  Bottom Layer w15: v1(1279.12,2162.9) 1279.12,2189.12 C126.1@1290,2200 C121.1@1340,2200 ; R202.1@1340,2140 C121.1@1340,2200 ; C116.1@1390,2190 1380,2200 C121.1@1340,2200
Vpu-1: L9.2 R15.2 R16.2 R19.2 R20.2 R29.2 R31.2 R33.2 R35.2 R37.2 R42.2 R43.2 R48.2 R49.2 R341.2 R343.2 R345.2 | length 1173.5
  Top Layer w6: v1(3145.75,2379.03) 3153.03,2379.03 3174,2400 R345.2@3198.8,2400
  Top Layer w10: v1(3724.41,2060.54) 3740,2076.12 R48.2@3740,2090
  SIGNAL LAYER w6: v1(3145.75,2379.03) 3201.38,2323.4 v1(3201.38,2051.2)
  Bottom Layer w6: v1(3201.38,2051.2) R341.2@3201.38,2090 ; R49.2@3720,2152.76 3720,2064.95 v1(3724.41,2060.54)
  Bottom Layer w10: v1(3145.75,2379.03) 3145.75,2405.91 3143.53,2408.14 3143.53,2432.32 3159.83,2448.62 R343.2@3174.77,2448.62
  Bottom Layer w15: v1(2952.76,2174.37) R29.2@2952.76,2200 R31.2@2952.76,2250 R33.2@2952.76,2300 R35.2@2952.76,2350 R37.2@2952.76,2400 ; R20.2@3289.89,1801.79 R19.2@3336.54,1801.79 3338.27,1803.52 3338.27,1826.61 v1(3340,1828.35) R16.2@3340,1850 R15.2@3402.76,1850 ; R42.2@3415.35,2103.62 3504.76,2103.62 R43.2@3505.62,2102.76 3520.03,2102.76 v1(3527.28,2110)
Vpu-2: L12.2 R68.2 R69.2 R72.2 R73.2 R82.2 R84.2 R86.2 R88.2 R90.2 R95.2 R96.2 R101.2 R102.2 R370.2 R372.2 R374.2 | length 2765.9
  Top Layer w6: L12.2@4633.15,2120 4633.15,2098.35 v1(4641.02,2090.47) ; v1(4815.74,2070.88) 4820,2075.14 R101.2@4820,2100
  Top Layer w12: v1(4155.65,2521.59) 4159.84,2525.77 4201.36,2525.77 R374.2@4221.19,2505.94 ; R372.2@4347.35,2360.73 4354.65,2353.42 v1(4354.65,2342.9)
  SIGNAL LAYER w6: v1(4641.02,2090.47) 4773.71,2090.47 4793.31,2070.88 v1(4815.74,2070.88)
  SIGNAL LAYER w10: v1(4354.65,2342.9) 4337.3,2325.54 4337.3,1972.7 v1(4430,1880)
  SIGNAL LAYER w12: v1(4155.65,2521.59) 4157.05,2521.59 4163.66,2528.2 4218.86,2528.2 4354.65,2392.4 v1(4354.65,2342.9)
  Bottom Layer w10: v1(4430,1678.35) R73.2@4430,1700 R72.2@4492.76,1700 ; v1(4430,1880) R69.2@4430,1850 R68.2@4492.76,1850
  Bottom Layer w12: R102.2@4808.54,2103.62 4808.54,2078.07 v1(4815.74,2070.88)
  Bottom Layer w15: v1(4155.65,2521.59) 4098.72,2521.59 4063.39,2486.25 4030,2452.86 R90.2@4030,2410 R88.2@4030,2360 R86.2@4030,2310 R84.2@4030,2260 R82.2@4030,2210 4030,2196.32 4147.91,2078.42 R370.2@4348.77,2078.42 4348.77,2056.79 4366.57,2039 4412.88,2039 4441,2067.12 4441,2098.62 4456.01,2113.63 R96.2@4485.59,2113.63 ; R95.2@4484.49,2161.8 4484.49,2114.73 R96.2@4485.59,2113.63 ; v1(4641.02,2090.47) 4664,2067.5 4664,2017 4652,2005 4524.71,2005 4485.59,2044.12 R96.2@4485.59,2113.63
Vpu-3: L15.2 R121.2 R122.2 R125.2 R126.2 R135.2 R137.2 R139.2 R141.2 R143.2 R148.2 R149.2 R154.2 R155.2 R378.2 R380.2 R382.2 | length 1042.8
  Top Layer w6: v1(2060.01,2309.39) 2060.01,2334.83 R380.2@2065.28,2340.1 ; v1@2616.26,2090 2635,2090 2640,2095 R154.2@2640,2120
  Top Layer w10: v1@1863.39,2200.5 1863.39,2233.39 1934.25,2304.25 R382.2@1971.38,2304.25
  Top Layer w25: L15.2@2466.57,2090 v1(2498.39,2090)
  Bottom Layer w6: R122.2@2237.24,1850 R121.2@2302.76,1850 ; R126.2@2240,1700 R125.2@2300,1700 ; v1(2616.49,2090) 2616.49,2118.37 2640,2141.88 R155.2@2640,2142.76
  Bottom Layer w10: v1(2237.24,1826.69) R122.2@2237.24,1850 ; R126.2@2240,1700 2240,1725.66 v1(2240.36,1725.66)
  Bottom Layer w15: R143.2@1860,2430 R141.2@1860,2380 R139.2@1860,2330 1862.76,2327.24 R137.2@1862.76,2280 R135.2@1862.76,2230 ; R378.2@1862.52,2170.14 v1@1862.52,2193.63 ; v1@1862.52,2199.63 1863.39,2200.5 v1@1862.76,2201.13 ; v1@1862.76,2195.13 R135.2@1862.76,2224 ; R148.2@2277.24,2150 2356.37,2070.88 2418.12,2070.88 R149.2@2440,2092.76 2495.63,2092.76 v1(2498.39,2090)
  other v1: 1863.39,2194.5
Vpu-4: L20.2 R174.2 R175.2 R178.2 R179.2 R188.2 R190.2 R192.2 R194.2 R196.2 R201.2 R202.2 R207.2 R208.2 R386.2 R388.2 R390.2 | length 1728.3
  Top Layer w10: v1(665,2200) 712.2,2247.2 857.28,2247.2 v1(885.08,2275) 885.08,2290.55 R390.2@871.38,2304.25 ; L20.2@1295.62,2102.76 1315.59,2102.76 v1(1318.35,2100) ; R207.2@1510,2070 1512.83,2067.16 v1(1540,2067.16)
  Bottom Layer w10: v1(1130,1721.65) 1127.24,1718.9 R179.2@1127.24,1700 R178.2@1194.13,1700 ; v1(1540,2067.16) R208.2@1540,2092.76
  Bottom Layer w15: R196.2@662.76,2430 R194.2@662.76,2380 R192.2@662.76,2330 R190.2@662.76,2280 662.07,2279.31 662.07,2230.69 R188.2@661.38,2230 664.04,2227.33 664.04,2175.46 R386.2@662.03,2173.44 662.03,2079.14 923.45,1817.72 1119.37,1817.72 v1(1130,1828.35) 1129.04,1829.3 1129.04,1848.2 R175.2@1127.24,1850 R174.2@1192.76,1850 ; R388.2@873.62,2333.35 885.08,2321.88 v1(885.08,2275) ; R201.2@1177.24,2150 1232.76,2150 1282.76,2100 v1(1318.35,2100) 1332.76,2100 R202.2@1340,2092.76
Vsleep1: C27.1 C28.1 C29.1 C30.1 L21.2 R23.1 U1.7 | length 1840.8
  Top Layer w9: U1.7@3550,2348.11 3571.33,2348.11 3580.78,2357.57 3703.6,2357.57 3741.03,2395 v1(3760,2395)
  Top Layer w10: L21.2@3790,1883.15 3792.12,1885.27 3792.12,1907.88 v2(3794.25,1910)
  SIGNAL LAYER w10: v1(3357.35,1512.01) 3421.16,1448.2 3536.2,1448.2 3794.25,1706.25 v2(3794.25,1910)
  Bottom Layer w10: v1(3357.35,1512.01) 3357.76,1512.42 R23.1@3357.76,1553.1 ; v1(3760,2395) 3762.71,2395 3767.77,2400.06 3769.36,2400.06 3774.74,2405.44 3807.35,2405.44 3885.52,2327.27 3885.52,1915.52 C29.1@3880,1910
  Bottom Layer w25: v2(3794.25,1910) C30.1@3830,1910 C29.1@3880,1910 C28.1@3930,1910 C27.1@3980,1910
Vsleep2: C61.1 C62.1 C63.1 C64.1 L22.2 R76.1 U7.7 | length 2063.8
  Top Layer w9: U7.7@4650,2348.11 4673.51,2348.11 4711.1,2385.7 4711.1,2402.56 4745.54,2437 4778.34,2437 4790.15,2425.19 4813.79,2425.19 v1(4848.98,2390)
  Top Layer w10: L22.2@4871.61,1882.4 4874.61,1885.39 4874.61,1903.16 v2(4877.6,1906.15)
  SIGNAL/POWER LAYER w10: v1(4396.55,1508) 4454.3,1450.24 4610.99,1450.24 4761.95,1601.21 4761.95,1734.44 4877.6,1850.09 v2(4877.6,1906.15)
  Bottom Layer w10: R76.1@4345.35,1647.94 4306.89,1647.94 4297.78,1638.83 4297.78,1535.98 4325.77,1508 v1(4396.55,1508) ; v1(4848.98,2390) 4852,2386.98 4852,2347.03 4846.61,2341.64 4846.61,2192.9 4950.52,2089 4950.52,1922.98 4956.35,1917.14 C63.1@4951.61,1917.14
  Bottom Layer w12: v2(4877.6,1906.15) 4895.36,1906.15 C64.1@4901.61,1912.4
  Bottom Layer w25: C64.1@4901.61,1912.4 C63.1@4951.61,1912.4 C62.1@5001.61,1912.4 C61.1@5051.61,1912.4
Vsleep3: C95.1 C96.1 C97.1 C98.1 L23.2 R129.1 U13.7 | length 2028.7
  Top Layer w9: U13.7@2450,2348.11 2471,2348.11 2476.25,2353.35 2485.61,2353.35 2498.33,2366.08 v1(2680.8,2366.08)
  Top Layer w20: L23.2@2685.51,1882.28 2685.51,1909.78 v2(2685.73,1910)
  SIGNAL/POWER LAYER w10: v1(2242.76,1490) 2278.96,1453.79 2429.47,1453.79 2559.7,1584.02 2596.04,1584.02 2660.07,1648.05 2660.07,1884.34 v2(2685.73,1910)
  Bottom Layer w10: R129.1@2169.06,1645.59 2130.59,1645.59 2121.48,1636.48 2121.48,1533.64 2165.12,1490 v1(2242.76,1490) ; v1(2680.8,2366.08) 2685.73,2361.14 2685.73,2197.49 2763.97,2119.26 2763.97,1923.82 C97.1@2775.51,1912.28
  Bottom Layer w20: v2(2685.73,1910) 2723.23,1910 C98.1@2725.51,1912.28 C97.1@2775.51,1912.28 C96.1@2825.51,1912.28 C95.1@2875.51,1912.28
Vsleep4: C129.1 C130.1 C131.1 C132.1 L24.2 R182.1 U19.7 | length 2001.1
  Top Layer w9: U19.7@1350,2348.11 1365,2348.11 1368.89,2352 1399,2352 1415.14,2368.14 1508.14,2368.14 v1(1510,2370)
  Top Layer w25: L24.2@1581.79,1870.31 1581.79,1897.89 v2(1583.9,1900)
  SIGNAL/POWER LAYER w10: v1(1132.76,1490) 1214.92,1407.83 1383.15,1407.83 1453.69,1478.38 1453.69,1593.81 1569.16,1709.28 1569.16,1885.26 v2(1583.9,1900)
  Bottom Layer w10: R182.1@1057.07,1645.59 1022.73,1611.25 1022.73,1545.13 1077.86,1490 v1(1132.76,1490) ; v1(1510,2370) 1510,2235.7 1621.79,2123.91 C132.1@1621.79,1917.16
  Bottom Layer w25: v2(1583.9,1900) 1601.06,1917.16 C132.1@1621.79,1917.16 C131.1@1671.79,1917.16 C130.1@1721.79,1917.16 C129.1@1771.79,1917.16
WAKE-1: J17.2 R23-1.2 R347.1 U1.8 | length 1576
  Top Layer w6: U1.8@3541.69,2367.79 U1.8@3550,2367.79 3569.8,2367.79 3574.57,2372.57 3697.39,2372.57 3739.82,2415 3753.18,2415 v1(3760.24,2422.06)
  SIGNAL LAYER w6: J17.2@3500,1620 3571.8,1691.8 3723.45,1691.8 3750,1718.35 3750,1880 3700.06,1929.94 3700.06,2049.5 3700.06,2150.5 3740,2190.44 3740,2403.28 3758.78,2422.06 v1(3760.24,2422.06)
  Bottom Layer w6: R23-1.2@3250,1616.26 3251.64,1617.9 R347.1@3307.92,1617.9 3329.77,1617.9 3357.52,1645.65 3357.52,1647.52 3380,1670 3450,1670 J17.2@3500,1620
WAKE-2: J32.2 R76-1.2 R376.1 U7.8 | length 1237.4
  Top Layer w6: U7.8@4650,2367.79 4661.36,2367.79 4684.56,2391 4684.56,2410.44 v1(4665,2430)
  SIGNAL LAYER w10: J32.2@4580,1620 4531.13,1668.87 4531.13,2171.44 4565.09,2205.4 4586.57,2205.4 4625.57,2244.4 4625.57,2408.92 4646.65,2430 v1(4665,2430)
  Bottom Layer w10: R376.1@4392.6,1600 4427.58,1600 4477.58,1550 R76-1.2@4480,1550 4490.73,1550 4560.73,1620 J32.2@4580,1620
WAKE-3: J47.2 R129-1.2 R384.1 U13.8 | length 1364.2
  Top Layer w6: U13.8@2450,2367.79 2450.56,2368.35 2479.39,2368.35 2494.98,2383.94 2628.94,2383.94 v1(2650,2405)
  SIGNAL LAYER w10: J47.2@2390,1620 2435,1665 2435,2237.5 2602.5,2405 v1(2650,2405)
  Bottom Layer w10: R384.1@2216.3,1591.7 2237.78,1591.7 2289.48,1540 R129-1.2@2290,1540 2310,1540 J47.2@2390,1620
WAKE-4: J62.2 R182-1.2 R392.1 U19.8 | length 1353.8
  Top Layer w6: U19.8@1350,2367.79 1389.76,2367.79 1412.47,2390.5 1487.37,2390.5 v1(1504.84,2407.97)
  SIGNAL LAYER w6: J62.2@1280,1620 1337.52,1677.52 1337.52,1937.6 1340,1940.08 1340,2200.6 1440,2300.6 1504.84,2300.6 1539.24,2335 1540,2335 1540,2372.81 v1(1504.84,2407.97)
  Bottom Layer w6: R392.1@1104.31,1590 1130.46,1590 R182-1.2@1178.87,1541.59 1210.92,1541.59 1280,1610.67 J62.2@1280,1620
WAKE_N: R2.2 R347.2 R376.2 R384.2 R392.2 | length 7014.1
  Top Layer w10: v1(1056.52,1558.23) 1062.76,1564.48 1293.37,1564.48 1335.52,1606.63 1335.52,1646.64 1353.36,1664.48 1434.61,1664.48 v1(1439.23,1659.86) ; v1(2192.76,1558.23) 2192.76,1620.76 2242,1670 v1(2580,1670) ; R2.2@2515,558.62 2538.72,582.34 2538.72,598.86 2562,622.15 2562,689.72 2485.89,765.84 2485.89,788 2469.3,804.59 2469.3,902.95 2516.35,950 v1(2520,950) ; v2@3665.01,1647.94 v2(3665.01,1648.86)
  SIGNAL LAYER w10: v1(2192.76,1558.23) 2152.2,1517.68 2152.2,1235.7 2437.9,950 v1(2520,950)
  SIGNAL/POWER LAYER w10: v1(1439.23,1659.86) 1457.9,1659.86 1526.93,1728.89 1526.93,1892.05 1598.64,1963.75 1924.61,1963.75 2110,1778.36 2110,1620 2171.76,1558.23 v1(2192.76,1558.23) ; v1(2580,1670) 2628.58,1718.58 2628.58,1905.96 2666.24,1943.61 3056.39,1943.61 3180,1820 3180,1579.11 3291.51,1467.6 3553.1,1467.6 3665.01,1579.51 v2(3665.01,1648.86) 3686.27,1670.13 3686.27,1757.66 3885.61,1957 3886.67,1957 3901.7,1972.03 4094.6,1972.03 4257.75,1808.87 4257.75,1574.76 4331.51,1501.01 4355.29,1501.01 4375.2,1520.92 v1(4375.2,1554.12)
  Bottom Layer w10: v1(1056.52,1558.23) 1057.07,1558.78 R392.2@1057.07,1590 ; R384.2@2169.06,1591.7 2169.06,1569.35 2180.17,1558.23 v1(2192.76,1558.23) ; R347.2@3307.92,1665.14 3333.95,1691.16 3499.67,1691.16 3519.71,1671.12 3642.75,1671.12 v2(3665.01,1648.86) ; R376.2@4345.35,1600 4345.35,1593.5 4375.2,1563.66 v1(4375.2,1554.12)
XI-1: R59.2 R271.1 U1.5 | length 143.1
  Top Layer w6: U1.5@3550,2308.74 3613.19,2308.74 R59.2@3625,2320.55 3640,2305.55 v1(3640,2300)
  Bottom Layer w6: v1@3640,2298 v1(3640,2300) 3640,2302.16 3650.35,2312.52 R271.1@3668,2312.52
XI-2: R112.2 R272.1 U7.5 | length 165.8
  Top Layer w6: U7.5@4650,2308.74 4704.58,2308.74 4719.01,2323.17 v1(4719.01,2325.42) 4748.92,2325.42 R112.2@4752.74,2329.25
  Bottom Layer w6: v1(4719.01,2325.42) 4722.8,2325.42 4728.23,2320 R272.1@4770,2320
XI-3: R165.2 R273.1 U13.5 | length 190.9
  Top Layer w6: U13.5@2450,2308.74 2573.48,2308.74 R165.2@2584.84,2320.11
  Top Layer w10: R165.2@2584.84,2320.11 2584.84,2328.47 v1(2596.98,2340.61)
  Bottom Layer w10: v1(2596.98,2340.61) 2609.84,2327.74 R273.1@2609.84,2320.11
XI-4: R218.2 R274.1 U19.5 | length 174.6
  Top Layer w6: U19.5@1350,2308.74 1443.39,2308.74 R218.2@1450.2,2315.55 1450.2,2321.14 v1(1475.2,2346.14)
  Bottom Layer w6: R274.1@1475.2,2315.55 v1(1475.2,2346.14)
XI_CLK-1: C33.1 R59.1 Y1.3 Y6.3 | length 225.1
  Top Layer w10: R59.1@3672.24,2320.55 3687.99,2320.55 3691.58,2324.14 3788.12,2324.14 3806.37,2342.38 Y1.3@3827.28,2342.38 3856.08,2371.18 3858.88,2371.18 3861.66,2373.97 3871.29,2373.97 C33.1@3874.08,2371.18
XI_CLK-2: C67.1 R112.1 Y2.3 Y7.3 | length 172.8
  Top Layer w6: R112.1@4799.99,2329.25 4882.6,2329.25 4895.78,2342.44 Y7.3@4909.48,2342.44
  Top Layer w10: v1(4892.24,2312.55) 4892.24,2312.98 4909.48,2330.21 4909.48,2342.44 Y2.3@4909.48,2351.44
  Bottom Layer w10: v1(4892.24,2312.55) C67.1@4892.24,2324.36
XI_CLK-3: C101.1 R165.1 Y3.3 Y8.3 | length 193
  Top Layer w10: R165.1@2632.09,2320.11 2716.07,2320.11 2729.26,2333.29 Y3.3@2752.81,2333.29 2785.76,2366.24 2802.06,2366.24 C101.1@2804.85,2363.46
XI_CLK-4: C135.1 R218.1 Y4.3 Y9.3 | length 212
  Top Layer w6: R218.1@1497.44,2315.55 1544.54,2315.55 1563.57,2334.58 1624.3,2334.58 Y4.3@1627.08,2337.36
  Top Layer w10: Y4.3@1627.08,2337.36 1660.84,2371.12 1682.45,2371.12 C135.1@1685.24,2368.34
XO-1: C34.1 R61.1 | length 50
  Bottom Layer w6: R61.1@4045,2638.62 C34.1@4095,2638.62
XO-2: R113.2 U7.4 | length 91.6
  Top Layer w6: U7.4@4650,2289.05 R113.2@4741.56,2289.05
XO-3: C102.1 R167.1 | length 50
  Bottom Layer w6: C102.1@1850,2510 R167.1@1850,2560
XO-4: R219.2 U19.4 | length 109.9
  Top Layer w6: U19.4@1350,2289.05 1426.69,2289.05 R219.2@1450.2,2265.55
Y0: R271.2 U31.3 | length 2377.2
  Top Layer w6: v1(3235,375) 3239.2,370.8 U31.3@3239.2,302.7 ; v1(3378.38,1230) 3570,1421.62 v1(3570,1540)
  SIGNAL/POWER LAYER w6: v1(3570,1540) 3570,1543.92 3550,1563.92 3550,1793.76 3756.31,2000.06 3756.31,2209.28 3717.59,2248 v1(3704.65,2248)
  Bottom Layer w6: v1(3235,375) 3234.21,375 3154.56,454.64 3154.56,541.16 3183.4,570 3263.28,570 3275,581.72 3275,619.01 3261.75,632.26 3261.75,708.37 3378.38,824.99 v1(3378.38,1230) ; R271.2@3668,2265.28 3687.38,2265.28 v1(3704.65,2248)
Y1: R272.2 U31.8 | length 3309.9
  Top Layer w6: v2(3179.56,474.84) 3188.02,483.29 U31.8@3188.02,534.99 ; v1(3405.23,994.03) 3426.55,1015.35 3715.41,1015.35 3800.06,1100 v1(4170,1100)
  SIGNAL/POWER LAYER w6: v1(4527.19,1400) 4770.62,1400 4846.48,1475.86 4846.48,1765.14 4938.59,1857.25 4938.59,2001.51 4960,2022.92 4960,2111.4 4833.62,2237.77 v1(4814.11,2237.77)
  Bottom Layer w6: v2(3179.56,474.84) 3182.24,477.52 3182.24,538.98 3188.1,544.84 3256.51,544.84 3288,576.33 3288,624.4 3274.75,637.64 3274.75,702.98 3405.23,833.46 v1(3405.23,994.03) ; v1(4170,1100) 4207.11,1100 4462.11,1355 4482.19,1355 v1(4527.19,1400) ; R272.2@4770,2272.76 4770,2268.82 4798.37,2240.45 4811.43,2240.45 v1(4814.11,2237.77)
Y2: R273.2 U31.5 | length 2455.4
  Top Layer w6: v1(3255,590) 3264.79,580.21 U31.5@3264.79,534.99
  SIGNAL LAYER w6: v1(2571.08,1621.28) 2641.6,1691.8 2903.6,1691.8 v1(3319,1276.4)
  SIGNAL/POWER LAYER w6: v1(2571.08,1621.28) 2552.08,1640.28 2552.08,1679.88 2573.4,1701.2 2573.4,1765.9 2611.18,1803.68 2611.18,1991.99 2664.95,2045.76 2664.95,2185.05 v1(2610,2240)
  Bottom Layer w6: v1(3255,590) 3248.75,596.24 3248.75,713.75 3316.89,781.89 3316.89,1274.29 v1(3319,1276.4)
  Bottom Layer w10: R273.2@2609.84,2272.86 2609.84,2247.27 2610,2247.11 v1(2610,2240)
Y3: R274.2 U31.7 | length 4564.2
  Top Layer w6: v1(1345,1569) 1443.04,1470.96 1443.04,1193.31 1697.68,938.66 1820.93,938.66 v1(1853.13,906.46) ; U31.7@3213.61,533.8 U31.7@3213.61,534.99 3213.61,577.41 v1(3227,590.8)
  SIGNAL LAYER w6: v1(1345,1569) 1432.7,1569 1518.58,1654.88 1518.58,1950.69 1489.37,1979.9 1489.37,2067.86 1454.47,2102.76 1454.47,2209.28 v1(1475.2,2230)
  Bottom Layer w6: v1(1475.2,2230) R274.2@1475.2,2268.31 ; v1(1853.13,906.46) 1912.18,965.52 1912.18,1132.18 2065,1285 2275,1285 2416.9,1426.9 2536.75,1426.9 2555,1408.65 2555,1268.77 2540,1253.77 2540,931.67 2551.72,919.96 2610.36,919.96 2634.7,944.3 2829.39,944.3 2859.46,914.23 3035.84,914.23 3084.62,963 3265.23,963 3303.89,924.34 3303.89,795.5 3227,718.61 v1(3227,590.8)
pads on no net: FID1.1 FID2.1 FID3.1 FID4.1 FID5.1 FID6.1 H1.1 H3.1 H5.0 H7.0 J1.8 J1.10 J1.11 J1.12 J1.13 J1.14 J1.16 J1.18 J1.20 J1.22 J1.24 J1.26 J1.27 J1.28 J1.29 J1.30 J1.31 J1.32 J1.33 J1.34 J1.35 J1.36 J1.37 J1.38 J1.41 J1.42 J1.43 J1.44 J1.45 J1.46 J1.47 J1.48 J1.49 J1.50 J1.51 J1.52 J1.54 J1.55 J1.56 J1.57 J1.58 J1.59 J1.60 J1.61 J1.62 J1.63 J1.64 J1.65 J1.66 J1.69 J1.70 J1.71 J1.72 J1.73 J1.74 J1.75 J1.76 J1.83 J1.84 J1.85 J1.86 J1.87 J1.88 J1.89 J1.90 J1.91 J1.92 J1.93 J1.94 J1.95 J1.96 J1.97 J1.98 J1.99 J1.101 J1.106 J1.107 J1.108 J1.109 J1.110 J1.111 J1.112 J1.113 J1.115 J1.117 J1.MH1 J1.MH2 J2.22 J2.31 J2.35 J2.61 J2.62 J2.64 J2.102 J2.104 J2.106 J2.109 J2.111 J2.113 J2.115 J2.116 J2.117 J2.118 J2.MH1 J2.MH2 J7.MH1 J7.MH2 J7.MH3 J7.MH4 J8.MH1 J8.MH2 J8.MH3 J8.MH4 J9.MH1 J9.MH2 J9.MH3 J9.MH4 J10.MH1 J10.MH2 J10.MH3 J10.MH4 LBL1.0 RN1.1 RN1.8 RN1.9 RN1.16 RN2.1 RN2.8 RN2.9 RN2.16 RN3.1 RN3.8 RN3.9 RN3.16 RN4.1 RN4.8 RN4.9 RN4.16 U2.3 U2.7 U4.3 U4.7 U5.3 U5.7 U6.3 U6.7 U8.3 U8.7 U10.2 U10.7 U10.8 U10.9 U10.10 U10.19 U10.24 U10.29@5282.83,2948.96 U12.3 U12.7 U18.3 U18.7 U24.3 U24.7 Y5.1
